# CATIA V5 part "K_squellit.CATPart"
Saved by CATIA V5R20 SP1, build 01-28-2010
Part number: squellit
Publications: "Longueurcadre", "largeurcadre", "distH_bras21", "distH_flasque"
Bounding box of the stored display mesh (mm): x 0 to 40, y -30 to 300, z 0 to 1000
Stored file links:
  G:\Khaled_CFAO_2011\SIL\SIL_GR2\zthiebault\Khaled\CAD_ThinkMOTION\K_squellit.CATPart
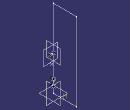
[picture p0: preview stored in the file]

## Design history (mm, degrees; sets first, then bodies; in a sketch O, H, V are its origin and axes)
Parameters
  Longueurcadre = 1000 mm
  largeurcadre = 300 mm
  distH_bras21 = 141.06 mm {= (7.206mm+0.9mm+6mm)*10}
  distH_flasque = 171.06 mm
Sketch1 on yz-plane, origin (0, 0, 0), H (0, 1, 0), V (0, 0, 1)
  line L1 (0, 0) -> (300, 0)
  line L2 (300, 0) -> (300, 1000)
  line L3 (300, 1000) -> (0, 1000)
  line L4 (0, 1000) -> (0, 0)
  point P4 (0, 80)
  point P5 (0, 160)
  length L2 = 1000 {= Longueurcadre}
  length L1 = 300 {= largeurcadre}
  distance P4 H = 80
  distance P5 H = 160
  horizontal: L1 H, L3 H
  vertical: L2 V, L4 V
  coincidence: P4 L4, P5 L4
Body1 (main body)
  Line1: stored without definition
  DatumPoint1
  Point1: stored without definition
  Point2: stored without definition
  DatumPoint2
  Line2: type Normal, RefPoint Sketch1.P4, RefSkin zx-plane, Start 0, End 30
  Line3: type Normal, RefPoint Sketch1.P5, RefSkin zx-plane, Start 0, End 30
  Plane1: type OffsetPt, RefPlane zx-plane, RefPoint Sketch1.P4
  Plane2: type OffsetPt, RefPlane zx-plane, RefPoint Sketch1.P5
  Point3: type OnCurve, Support Sketch1.L4, Length 550
  Plane3: type OffsetPt, RefPlane yz-plane, RefPoint Point3
  Line4: type Normal, RefPoint Point3, RefSkin Plane3, Start 0, End 40
  Point4: type OnCurve, Support Line4, Length 37.273
  Plane4: type OffsetPt, RefPlane zx-plane, RefPoint Point4
  Line5: type Normal, RefPoint Point4, RefSkin Plane4, Start 0, End 23.72
  DatumCurve1
  Point5: type OnCurve, Support Line5, Length 15.5
  DatumCurve2
  Point6: type Center, Curve DatumCurve2
  Plane5: type OffsetPt, RefPlane zx-plane, RefPoint Sketch1.P4
  Plane6: type OffsetPt, RefPlane zx-plane, RefPoint Sketch1.P5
